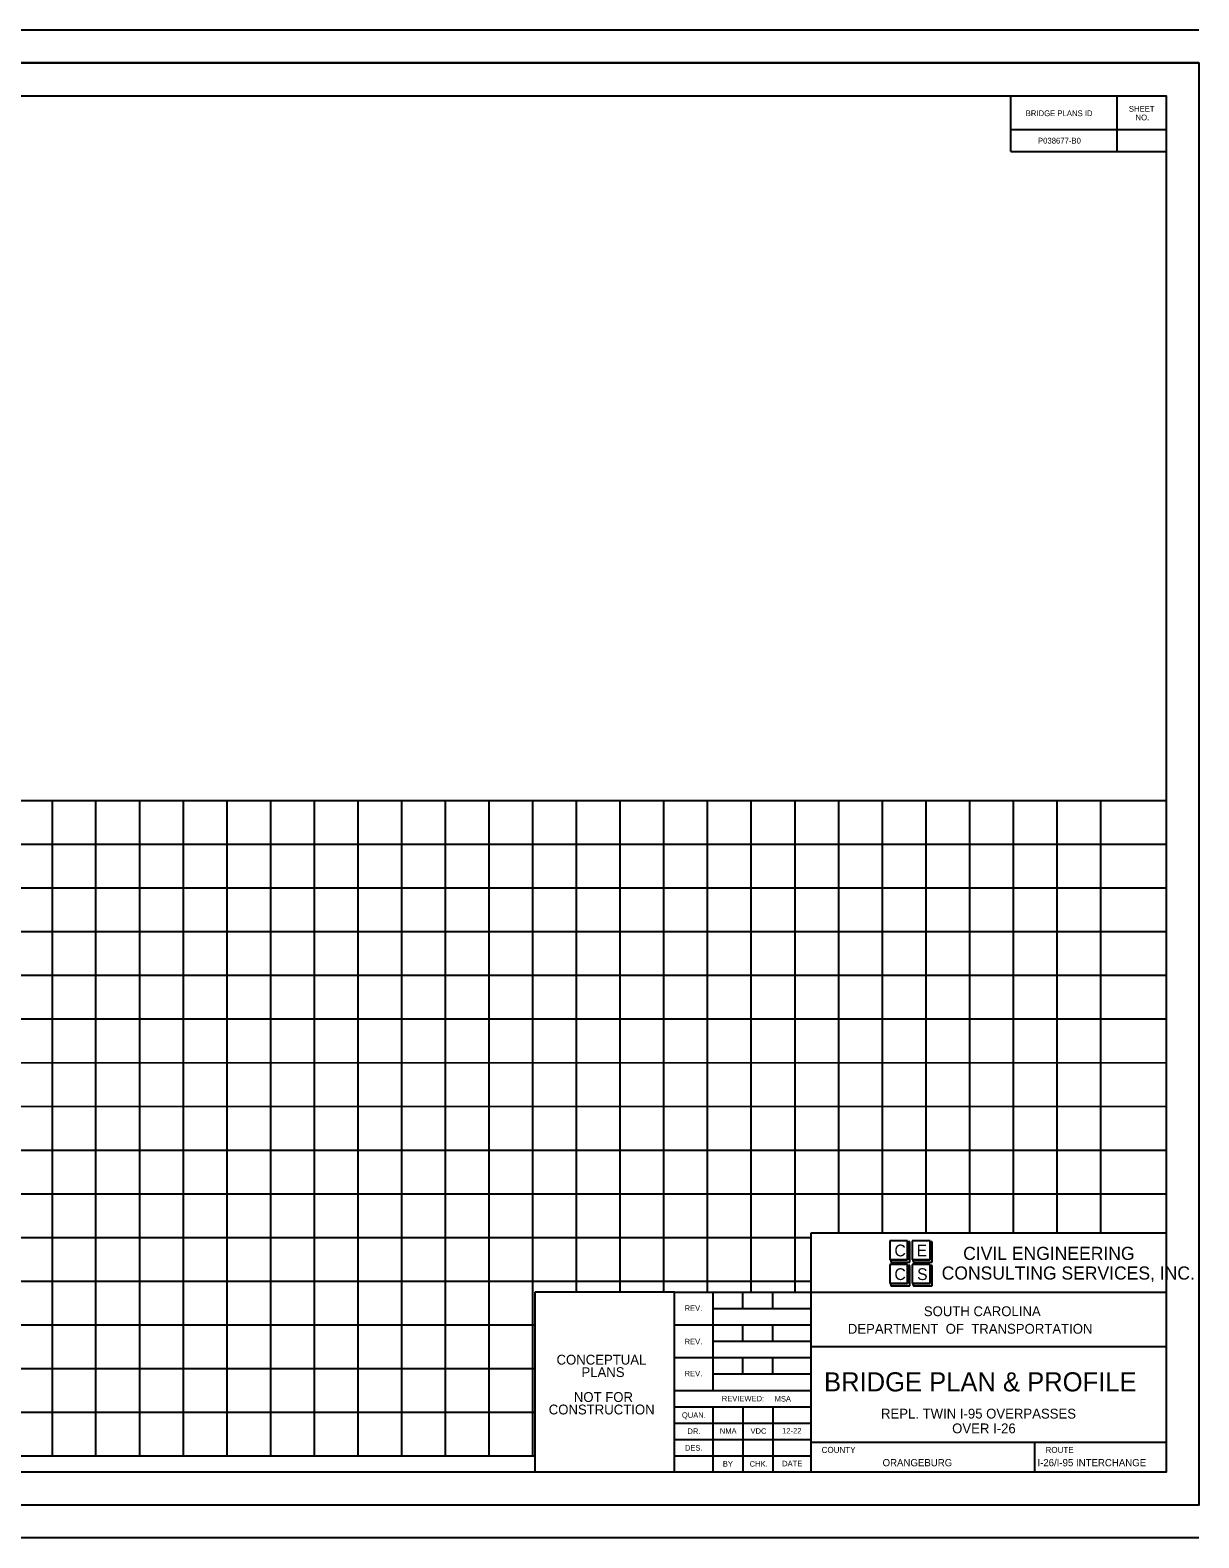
# Model space of a CAD drawing. Extents: x 1876043.9 to 1876079.9, y 869049.3 to 869072.3.
# Drawn here: x 1876062.11 to 1876079.94, y 869049.33 to 869072.33 of the extents above; entities that cross this region are included whole.
import ezdxf

# ---------------------------------------------------------------- set-up
doc = ezdxf.new("R2010")
doc.units = 0
for name, color, linetype in [('BR_TEXT', 7, 'Continuous'), ('Level 1', 7, 'Continuous'), ('Level 2', 7, 'Continuous'), ('Level 3', 7, 'Continuous'), ('Level 4', 7, 'Continuous'), ('Level 5', 7, 'Continuous'), ('Level 63', 7, 'Continuous'), ('Level 7', 7, 'Continuous')]:
    doc.layers.add(name, color=color, linetype=linetype)

msp = doc.modelspace()

# ---------------------------------------------------------------- linework, layer by layer
at = {"layer": 'Level 1'}
for p, q in [((1876079.944, 869072.33), (1876044.744, 869072.331)), ((1876079.944, 869071.83), (1876044.744, 869071.831)), ((1876045.444, 869060.581), (1876079.444, 869060.58)), ((1876062.444, 869060.581), (1876062.444, 869050.581)), ((1876065.777, 869060.581), (1876065.777, 869050.58)), ((1876069.111, 869060.581), (1876069.111, 869050.58)), ((1876072.444, 869060.58), (1876072.444, 869053.08)), ((1876075.777, 869060.58), (1876075.777, 869053.985)), ((1876078.444, 869060.58), (1876078.444, 869053.985)), ((1876045.444, 869050.581), (1876069.81, 869050.58)), ((1876045.444, 869050.581), (1876069.81, 869050.58)), ((1876079.944, 869049.83), (1876044.744, 869049.831)), ((1876079.944, 869049.83), (1876079.944, 869049.83)), ((1876079.944, 869049.33), (1876044.744, 869049.331))]:
    msp.add_line(p, q, dxfattribs=at)
msp.add_lwpolyline([(1876045.444, 869071.33), (1876079.444, 869071.33), (1876079.444, 869050.33), (1876045.444, 869050.33)], close=True, dxfattribs=at)
msp.add_lwpolyline([(1876045.444, 869071.33), (1876079.444, 869071.33), (1876079.444, 869050.33), (1876045.444, 869050.33)], close=True, dxfattribs=at)
at = {"layer": 'Level 2'}
for p, q in [((1876074.027, 869053.985), (1876079.441, 869053.985)), ((1876074.027, 869050.33), (1876074.027, 869053.985)), ((1876071.944, 869053.08), (1876069.81, 869053.08)), ((1876069.81, 869053.08), (1876069.81, 869050.33)), ((1876071.944, 869053.08), (1876079.444, 869053.08)), ((1876071.944, 869050.33), (1876071.944, 869053.08)), ((1876072.527, 869053.08), (1876072.527, 869051.58)), ((1876072.985, 869052.83), (1876072.985, 869053.08)), ((1876073.444, 869052.83), (1876073.444, 869053.08)), ((1876072.527, 869052.83), (1876074.027, 869052.83)), ((1876071.944, 869052.58), (1876074.027, 869052.58)), ((1876072.985, 869052.33), (1876072.985, 869052.58)), ((1876073.444, 869052.33), (1876073.444, 869052.58)), ((1876072.527, 869052.33), (1876074.027, 869052.33)), ((1876074.027, 869052.247), (1876079.444, 869052.247)), ((1876071.944, 869052.08), (1876074.027, 869052.08)), ((1876072.985, 869051.83), (1876072.985, 869052.08)), ((1876073.444, 869051.83), (1876073.444, 869052.08)), ((1876072.527, 869051.83), (1876074.027, 869051.83)), ((1876071.944, 869051.58), (1876074.027, 869051.58)), ((1876071.944, 869051.33), (1876074.027, 869051.33)), ((1876072.527, 869051.33), (1876072.527, 869050.33)), ((1876072.985, 869051.33), (1876072.985, 869050.33)), ((1876073.444, 869051.33), (1876073.444, 869050.33)), ((1876071.944, 869051.08), (1876074.027, 869051.08)), ((1876071.944, 869050.83), (1876074.027, 869050.83)), ((1876074.027, 869050.791), (1876079.444, 869050.791)), ((1876077.444, 869050.331), (1876077.444, 869050.789)), ((1876071.944, 869050.58), (1876074.027, 869050.58))]:
    msp.add_line(p, q, dxfattribs=at)
at = {"layer": 'Level 3'}
for p, q in [((1876077.074, 869070.481), (1876077.074, 869071.316)), ((1876078.698, 869070.481), (1876078.698, 869071.316)), ((1876077.074, 869070.814), (1876079.433, 869070.814)), ((1876077.074, 869070.481), (1876079.433, 869070.481))]:
    msp.add_line(p, q, dxfattribs=at)
at = {"layer": 'Level 5'}
for p, q in [((1876063.11, 869060.581), (1876063.11, 869050.58)), ((1876063.777, 869060.581), (1876063.777, 869050.58)), ((1876064.444, 869060.581), (1876064.444, 869050.58)), ((1876065.11, 869060.581), (1876065.11, 869050.58)), ((1876066.444, 869060.581), (1876066.444, 869050.58)), ((1876067.11, 869060.581), (1876067.11, 869050.58)), ((1876067.777, 869060.581), (1876067.777, 869050.58)), ((1876068.444, 869060.581), (1876068.444, 869050.58)), ((1876069.777, 869060.581), (1876069.777, 869050.58)), ((1876070.444, 869060.58), (1876070.444, 869053.08)), ((1876071.11, 869060.58), (1876071.11, 869053.08)), ((1876071.777, 869060.58), (1876071.777, 869053.08)), ((1876073.11, 869060.58), (1876073.11, 869053.08)), ((1876073.777, 869060.58), (1876073.777, 869053.08)), ((1876074.444, 869060.58), (1876074.444, 869053.985)), ((1876075.11, 869060.58), (1876075.11, 869053.985)), ((1876076.444, 869060.58), (1876076.444, 869053.985)), ((1876077.11, 869060.58), (1876077.11, 869053.985)), ((1876077.777, 869060.58), (1876077.777, 869053.985)), ((1876045.444, 869059.913), (1876079.444, 869059.912)), ((1876045.444, 869059.247), (1876079.444, 869059.246)), ((1876045.444, 869058.58), (1876079.444, 869058.579)), ((1876045.444, 869057.914), (1876079.444, 869057.913)), ((1876045.444, 869057.247), (1876079.444, 869057.246)), ((1876045.444, 869056.58), (1876079.444, 869056.579)), ((1876045.444, 869055.914), (1876079.444, 869055.913)), ((1876045.444, 869055.247), (1876079.444, 869055.246)), ((1876045.444, 869054.581), (1876079.444, 869054.58)), ((1876045.444, 869053.914), (1876074.027, 869053.913)), ((1876045.444, 869053.247), (1876074.027, 869053.247)), ((1876045.444, 869052.581), (1876069.81, 869052.58)), ((1876045.444, 869051.914), (1876069.81, 869051.913)), ((1876045.444, 869051.248), (1876069.81, 869051.247))]:
    msp.add_line(p, q, dxfattribs=at)
at = {"layer": 'Level 63'}
msp.add_lwpolyline([(1876043.944, 869071.83), (1876079.944, 869071.83), (1876079.944, 869049.83), (1876043.944, 869049.83)], close=True, dxfattribs=at)
at = {"layer": 'Level 7'}
for p, q in [((1876075.5, 869053.862), (1876075.227, 869053.862)), ((1876075.227, 869053.862), (1876075.227, 869053.573)), ((1876075.5, 869053.573), (1876075.5, 869053.862)), ((1876075.5, 869053.862), (1876075.5, 869053.573)), ((1876075.534, 869053.844), (1876075.5, 869053.844)), ((1876075.534, 869053.537), (1876075.534, 869053.844)), ((1876075.842, 869053.862), (1876075.569, 869053.862)), ((1876075.569, 869053.862), (1876075.569, 869053.573)), ((1876075.842, 869053.573), (1876075.842, 869053.862)), ((1876075.842, 869053.862), (1876075.842, 869053.573)), ((1876075.876, 869053.844), (1876075.842, 869053.844)), ((1876075.876, 869053.537), (1876075.876, 869053.844)), ((1876075.227, 869053.573), (1876075.5, 869053.573)), ((1876075.5, 869053.573), (1876075.244, 869053.573)), ((1876075.244, 869053.573), (1876075.244, 869053.537)), ((1876075.244, 869053.537), (1876075.534, 869053.537)), ((1876075.569, 869053.573), (1876075.842, 869053.573)), ((1876075.842, 869053.573), (1876075.586, 869053.573)), ((1876075.586, 869053.573), (1876075.586, 869053.537)), ((1876075.586, 869053.537), (1876075.876, 869053.537)), ((1876075.5, 869053.501), (1876075.227, 869053.501)), ((1876075.227, 869053.501), (1876075.227, 869053.212)), ((1876075.5, 869053.212), (1876075.5, 869053.501)), ((1876075.5, 869053.501), (1876075.5, 869053.212)), ((1876075.534, 869053.483), (1876075.5, 869053.483)), ((1876075.534, 869053.176), (1876075.534, 869053.483)), ((1876075.842, 869053.501), (1876075.569, 869053.501)), ((1876075.569, 869053.501), (1876075.569, 869053.212)), ((1876075.842, 869053.212), (1876075.842, 869053.501)), ((1876075.842, 869053.501), (1876075.842, 869053.212)), ((1876075.876, 869053.483), (1876075.842, 869053.483)), ((1876075.876, 869053.176), (1876075.876, 869053.483)), ((1876075.227, 869053.212), (1876075.5, 869053.212)), ((1876075.5, 869053.212), (1876075.244, 869053.212)), ((1876075.244, 869053.212), (1876075.244, 869053.176)), ((1876075.244, 869053.176), (1876075.534, 869053.176)), ((1876075.569, 869053.212), (1876075.842, 869053.212)), ((1876075.842, 869053.212), (1876075.586, 869053.212)), ((1876075.586, 869053.212), (1876075.586, 869053.176)), ((1876075.586, 869053.176), (1876075.876, 869053.176))]:
    msp.add_line(p, q, dxfattribs=at)

# ---------------------------------------------------------------- texts
at = {"layer": 'BR_TEXT'}
msp.add_text('BRIDGE PLAN & PROFILE', height=0.29167, dxfattribs=at).set_placement((1876074.225, 869051.564))
at = {"layer": 'Level 2'}
for s, p in [('REV.', (1876072.098, 869052.794)), ('REV.', (1876072.098, 869052.283)), ('REV.', (1876072.098, 869051.794)), ('REVIEWED:', (1876072.665, 869051.413)), ('MSA', (1876073.471, 869051.409)), ('QUAN.', (1876072.056, 869051.161)), ('DR.', (1876072.141, 869050.916)), ('NMA', (1876072.635, 869050.918)), ('VDC', (1876073.103, 869050.918)), ('12-22', (1876073.586, 869050.922)), ('DES.', (1876072.102, 869050.661)), ('BY', (1876072.681, 869050.418)), ('CHK.', (1876073.09, 869050.417)), ('DATE', (1876073.586, 869050.422))]:
    msp.add_text(s, height=0.0833, dxfattribs=at).set_placement(p)
at = {"layer": 'Level 3'}
for s, height, p in [('BRIDGE PLANS ID', 0.088, (1876077.302, 869071.019)), ('SHEET', 0.088, (1876078.876, 869071.087)), ('NO.', 0.088, (1876078.978, 869070.955)), ('P038677-B0', 0.088, (1876077.49, 869070.601)), ('COUNTY', 0.0917, (1876074.188, 869050.626)), ('I-26/I-95 INTERCHANGE', 0.11, (1876077.481, 869050.422)), ('ROUTE', 0.0917, (1876077.605, 869050.626)), ('ORANGEBURG', 0.11, (1876075.118, 869050.422))]:
    msp.add_text(s, height=height, dxfattribs=at).set_placement(p)
at = {"layer": 'Level 4'}
for s, p in [('SOUTH CAROLINA', (1876075.748, 869052.712)), ('DEPARTMENT  OF  TRANSPORTATION', (1876074.588, 869052.444)), ('CONCEPTUAL', (1876070.143, 869051.973)), ('PLANS', (1876070.523, 869051.783)), ('NOT FOR', (1876070.407, 869051.403)), ('CONSTRUCTION', (1876070.024, 869051.213)), ('REPL. TWIN I-95 OVERPASSES', (1876075.094, 869051.15)), ('OVER I-26', (1876076.18, 869050.925))]:
    msp.add_text(s, height=0.15, dxfattribs=at).set_placement(p)
at = {"layer": 'Level 7'}
for s, height, p in [('C', 0.18, (1876075.299, 869053.624)), ('E', 0.18, (1876075.637, 869053.624)), ('CIVIL ENGINEERING', 0.2, (1876076.348, 869053.57)), ('C', 0.18, (1876075.299, 869053.263)), ('S', 0.18, (1876075.645, 869053.263)), ('CONSULTING SERVICES, INC.', 0.2, (1876076.02, 869053.27))]:
    msp.add_text(s, height=height, dxfattribs=at).set_placement(p)

doc.saveas('drawing.dxf')
